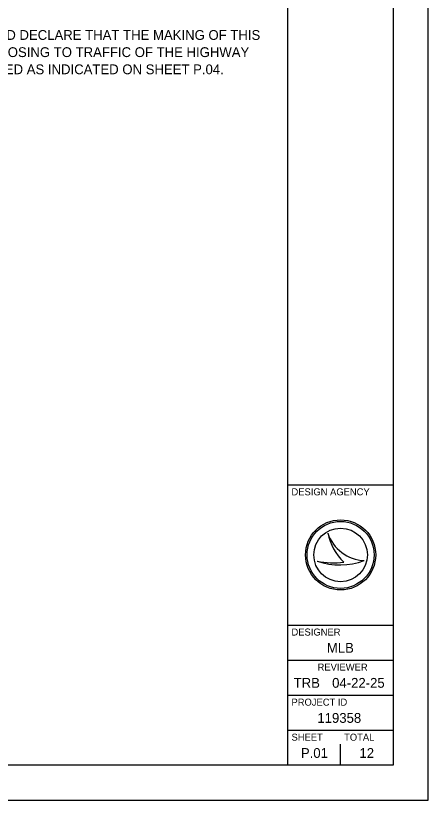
# Model space of a CAD drawing. Extents: x 0 to 34, y 0 to 22.
# Drawn here: x 28.12 to 34, y 0 to 11.19 of the extents above; entities that cross this region are included whole.
import ezdxf

# ---------------------------------------------------------------- set-up
doc = ezdxf.new("R2010")
doc.units = 0
for name, color, linetype in [('SH_Border', 7, 'Continuous'), ('SH_Cut_Line', 7, 'Continuous'), ('SH_Data', 7, 'Continuous'), ('SH_Text', 7, 'Continuous')]:
    doc.layers.add(name, color=color, linetype=linetype)

msp = doc.modelspace()

# ---------------------------------------------------------------- linework, layer by layer
at = {"layer": 'SH_Border'}
for p, q in [((32, 0.5), (32, 21.5)), ((32, 4.5), (33.5, 4.5)), ((32, 2.5), (33.5, 2.5)), ((32, 2), (33.5, 2)), ((32, 1.5), (33.5, 1.5)), ((32, 1), (33.5, 1))]:
    msp.add_line(p, q, dxfattribs=at)
msp.add_lwpolyline([(1.5, 21.5), (33.5, 21.5), (33.5, 0.5), (1.5, 0.5)], close=True, dxfattribs=at)
at = {"layer": 'SH_Cut_Line'}
msp.add_lwpolyline([(0, 0), (34, 0), (34, 22), (0, 22)], close=True, dxfattribs=at)
at = {"layer": 'SH_Data'}
for p, q in [((32.567, 3.81), (32.567, 3.81)), ((32.75, 3.5), (32.75, 3.5)), ((32.417, 3.41), (32.417, 3.41)), ((33.087, 3.419), (33.087, 3.419)), ((32.75, 0.5), (32.75, 0.8)), ((32.375, 0.675), (32.375, 0.675))]:
    msp.add_line(p, q, dxfattribs=at)
for radius in [0.5, 0.477, 0.477, 0.382]:
    msp.add_circle((32.75, 3.5), radius, dxfattribs=at)
for centre, radius, start, end in [((33.116, 3.998), 0.58, 198.9257, 198.9319), ((33.347, 3.97), 0.796, 191.6379, 191.6421), ((33.116, 3.998), 0.58, 198.9319, 267.1657), ((33.347, 3.97), 0.796, 191.6421, 226.0947), ((32.739, 4.37), 1.013, 251.4576, 290.0832), ((32.648, 4.654), 1.266, 259.4964, 259.4995), ((32.739, 4.37), 1.013, 251.4527, 251.4576), ((32.648, 4.654), 1.266, 259.4995, 276.6672)]:
    msp.add_arc(centre, radius, start, end, dxfattribs=at)

# ---------------------------------------------------------------- texts
for s, height, p in [('DESIGN AGENCY', 0.1, (32.05, 4.35)), ('DESIGNER', 0.1, (32.05, 2.35)), ('MLB', 0.14, (32.554, 2.105)), ('REVIEWER', 0.1, (32.422, 1.85)), ('TRB', 0.14, (32.081, 1.605)), ('04-22-25', 0.14, (32.629, 1.605)), ('PROJECT ID', 0.1, (32.05, 1.35)), ('119358', 0.14, (32.419, 1.105)), ('SHEET', 0.1, (32.05, 0.85)), ('TOTAL', 0.1, (32.8, 0.85)), ('P.01', 0.14, (32.184, 0.605)), ('12', 0.14, (33.019, 0.605))]:
    msp.add_text(s, height=height, dxfattribs=at).set_placement(p)
at = {"layer": 'SH_Text'}
for s, p in [('I HEREBY APPROVE THESE PLANS AND DECLARE THAT THE MAKING OF THIS ', (24.5, 10.846)), ('IMPROVEMENT WILL REQUIRE THE CLOSING TO TRAFFIC OF THE HIGHWAY ', (24.5, 10.601)), ('AND THAT DETOURS WILL BE PROVIDED AS INDICATED ON SHEET P.04.', (24.5, 10.356))]:
    msp.add_text(s, height=0.14, dxfattribs=at).set_placement(p)

doc.saveas('drawing.dxf')
